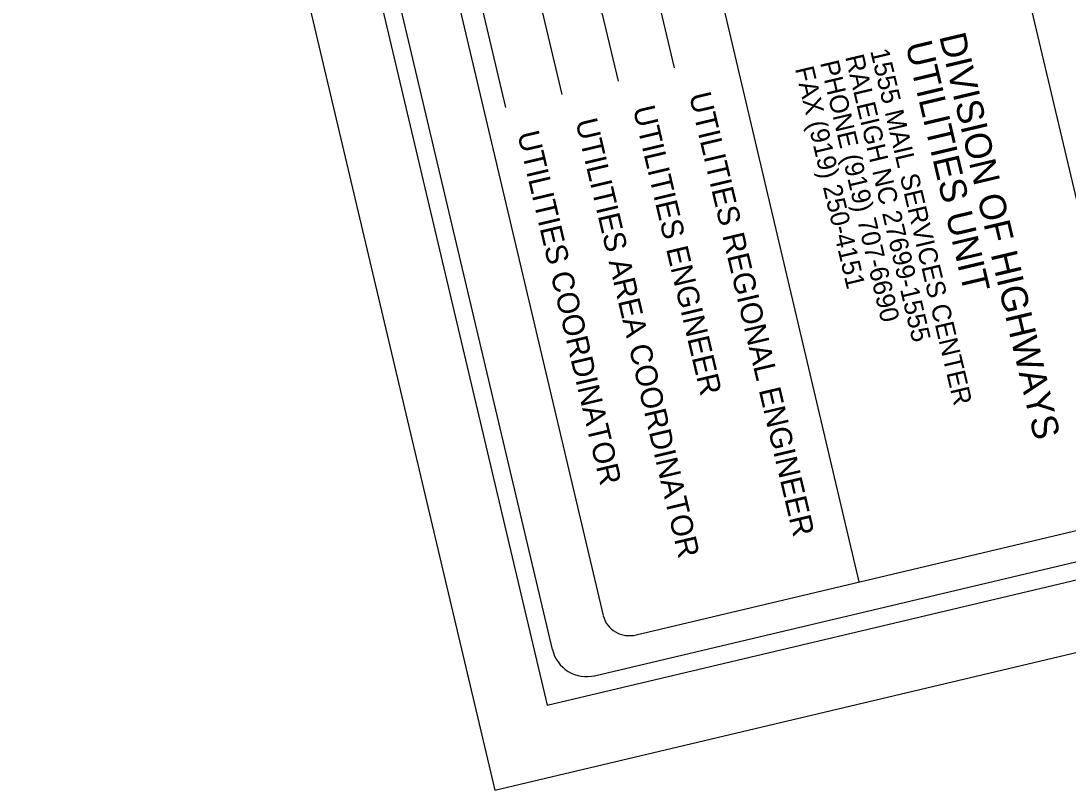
# Model space of a CAD drawing. Extents: x 1439200 to 1641919, y 393684 to 606444.
# Drawn here: x 1440332 to 1441638, y 598050 to 599009 of the extents above; entities that cross this region are included whole.
import ezdxf

# ---------------------------------------------------------------- set-up
doc = ezdxf.new("R2010")
doc.units = 0
doc.layers.add('Level 43', color=7, linetype='Continuous')
doc.layers.add('Old_Level_20', color=7, linetype='Continuous')

msp = doc.modelspace()

# ---------------------------------------------------------------- linework, layer by layer
at = {"layer": 'Level 43'}
for p, q in [((1441491.5, 599450.7), (1441733.6, 598426.6)), ((1441121, 599397), (1441377.4, 598309.6)), ((1441054.7, 599339.8), (1441146.9, 598950.6)), ((1440984.6, 599323.2), (1441076.8, 598934)), ((1440914.5, 599306.6), (1441006.7, 598917.4)), ((1440816.5, 599289.4), (1441058.1, 598267.6)), ((1440844.4, 599290), (1440936.5, 598900.8)), ((1441099.5, 598243.6), (1441707.5, 598387.5))]:
    msp.add_line(p, q, dxfattribs=at)
msp.add_lwpolyline([(1445632.9, 599164.9), (1443909.8, 606443.8), (1439200, 605328.8), (1440923.1, 598050)], close=True, dxfattribs=at)
for points in [[(1439494.5, 604562.1), (1440994.6, 598225.2)], [(1441047.6, 598192.5), (1445457.7, 599236.5)]]:
    msp.add_lwpolyline(points, dxfattribs=at)
msp.add_arc((1441037.7, 598235.4), 44, 193.3181, 283.3181, dxfattribs=at)
msp.add_ellipse((1441092.2, 598275.3), major_axis=(-33.8, -8), ratio=0.941469, start_param=6.282951, end_param=7.853377, dxfattribs=at)
at = {"layer": 'Old_Level_20'}
msp.add_lwpolyline([(1439298.8, 605293.4), (1440988.4, 598155.9), (1445527, 599230.3), (1443837.3, 606367.8)], close=True, dxfattribs=at)

# ---------------------------------------------------------------- texts
at = {"layer": 'Level 43'}
for s, height, p in [('UTILITIES UNIT', 32.969, (1441435.3, 598980)), ('DIVISION OF HIGHWAYS', 32.969, (1441477.4, 598990)), ('1555 MAIL SERVICES CENTER', 23.423, (1441391.4, 598971.7)), ('PHONE (919) 707-6690', 23.423, (1441328.8, 598956.9)), ('RALEIGH NC 27699-1555', 23.423, (1441360.1, 598964.3)), ('FAX (919) 250-4151', 23.423, (1441297.5, 598949.5)), ('UTILITIES REGIONAL ENGINEER', 27.199, (1441165.3, 598916.7)), ('UTILITIES ENGINEER', 27.199, (1441095.2, 598900)), ('UTILITIES AREA COORDINATOR', 27.199, (1441023.5, 598884.1)), ('UTILITIES COORDINATOR', 27.199, (1440951, 598868.5))]:
    msp.add_text(s, height=height, rotation=283.3038, dxfattribs=at).set_placement(p)

doc.saveas('drawing.dxf')
